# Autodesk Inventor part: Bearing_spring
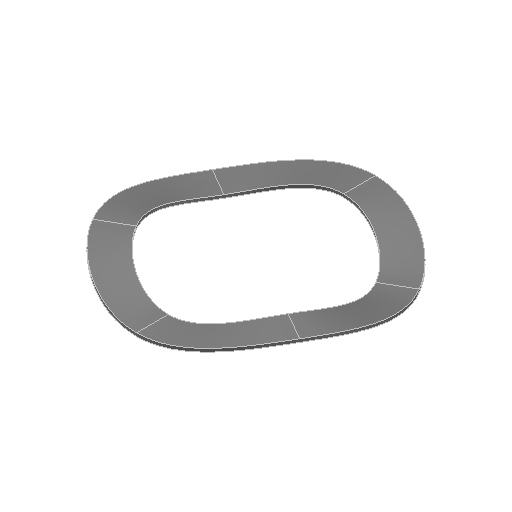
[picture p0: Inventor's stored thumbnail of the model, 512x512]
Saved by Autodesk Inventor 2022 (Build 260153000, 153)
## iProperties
Created: 2020-10
Part Number: Bearing_spring
Material: Generico
Document SubType Name: Modeling
Designer: admin
Density: 1 g/cm^3
Appearance: Default
Author: admin
Sending System: SolidWorks 2020
Last Author: Simon
Last Saved: 2020-10-31
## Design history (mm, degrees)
feature "Wrap1"
feature "Thicken1" [Wrap]
node "Solido1"
node "Solido2"
